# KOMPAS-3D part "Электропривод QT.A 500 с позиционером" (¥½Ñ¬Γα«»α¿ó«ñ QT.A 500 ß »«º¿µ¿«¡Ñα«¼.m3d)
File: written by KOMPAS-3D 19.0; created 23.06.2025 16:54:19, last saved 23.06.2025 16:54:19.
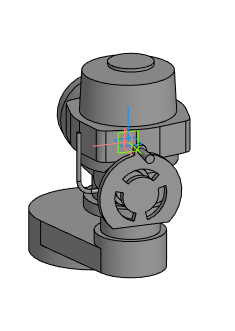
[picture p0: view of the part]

Document properties: Автор: Евгений; Полное имя файла: E:\Dendor Работа Сачек\3D для проектировщиков\3.5 Тип QT.А Электропривод\stp_Электропривод QT.A с позиционером\Электропривод QT.A 500 с позиционером.m3d

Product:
- Part/product: Электропривод QT.A 500 с позиционером

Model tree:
1. Операция без истории:1  (labels: Электропривод QT.A 500 с позиционером)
